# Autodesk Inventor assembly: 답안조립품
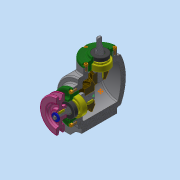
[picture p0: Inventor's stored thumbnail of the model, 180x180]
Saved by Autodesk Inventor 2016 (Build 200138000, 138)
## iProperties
Created: 2021-04
Part Number: 답안조립품
Document SubType Name: Assembly
Designer: User
Author: User
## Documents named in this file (17)
- C:\Users\User\Desktop\710407V1003\답안조립품.iam
- C:\Users\User\Desktop\710407V1003\본체.ipt
- C:\Users\User\Desktop\710407V1003\메인 축.ipt
- 메인 축.ipt
- C:\Users\User\Desktop\710407V1003\서브 축.ipt
- 서브 축.ipt
- C:\Users\User\Desktop\710407V1003\키 5 x 5 x 14.ipt
- C:\Users\User\Desktop\710407V1003\키 4 x 4 x 14.ipt
- C:\Users\User\Desktop\710407V1003\메인 베벨기어.ipt
- C:\Users\User\Desktop\710407V1003\서브 베벨기어.ipt
- C:\Users\User\Desktop\710407V1003\오일실 17 x 32 x 8.ipt
- C:\Users\User\Desktop\710407V1003\커버.ipt
- C:\Users\User\Desktop\710407V1003\베어링 6203.ipt
- C:\Users\User\Desktop\710407V1003\V-벨트풀리.ipt
- C:\Users\User\Desktop\710407V1003\볼트 M4 x 10.ipt
- C:\Users\User\Desktop\710407V1003\와셔 4 x 16.ipt
- C:\Users\User\Desktop\710407V1003\육각볼트 M4 x 8.ipt
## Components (1 placed, 1 different names)
1. V-벨트풀리:1
